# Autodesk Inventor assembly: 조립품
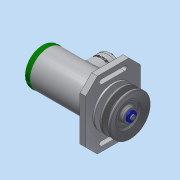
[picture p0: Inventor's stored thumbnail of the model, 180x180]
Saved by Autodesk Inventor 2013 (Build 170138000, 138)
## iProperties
Created: 2017-10
Part Number: 조립품
Document SubType Name: Assembly
Designer: dgall
Author: dgall
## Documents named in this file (20)
- C:\Users\dgall\Desktop\471007V1023\조립품.iam
- C:\Users\dgall\Desktop\471007V1023\본체.ipt
- C:\Users\dgall\Desktop\471007V1023\축.ipt
- C:\Users\dgall\Desktop\471007V1023\베어링 15 x 35 x 11.ipt
- C:\Users\dgall\Desktop\471007V1023\십자볼트 M3 x 10.ipt
- C:\Users\dgall\Desktop\471007V1023\와셔 4x16.ipt
- C:\Users\dgall\Desktop\471007V1023\탑 커버.ipt
- C:\Users\dgall\Desktop\471007V1023\볼트 M4 x 10.ipt
- C:\Users\dgall\Desktop\471007V1023\V-벨트풀리.ipt
- C:\Users\dgall\Desktop\471007V1023\키 4 x 4 x 18.ipt
- C:\Users\dgall\Desktop\471007V1023\오일 실 15 25 7.ipt
- C:\Users\dgall\Desktop\471007V1023\너트 M10.ipt
- C:\Users\dgall\Desktop\471007V1023\와셔 10x21.ipt
- C:\Users\dgall\Desktop\471007V1023\멈춤링 35x1.6.ipt
- C:\Users\dgall\Desktop\471007V1023\부시1.ipt
- C:\Users\dgall\Desktop\471007V1023\부시2.ipt
- C:\Users\dgall\Desktop\471007V1023\와셔 3x6.ipt
- C:\Users\dgall\Desktop\471007V1023\멈춤링 15 x 1.ipt
- C:\Users\dgall\Desktop\471007V1023\사이드 커버.ipt
- 사이드 커버.ipt
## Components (2 placed, 2 different names)
1. ISO 4017 M4 x 10:1
2. V-벨트풀리:1
